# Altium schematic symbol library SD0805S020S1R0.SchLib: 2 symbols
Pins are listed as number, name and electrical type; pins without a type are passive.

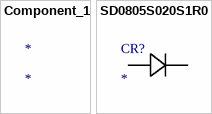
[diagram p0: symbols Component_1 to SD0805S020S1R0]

## Component_1
designator *

## SD0805S020S1R0
designator CR?
No Description Available; Mfr_Name: KYOCERA AVX
footprint SD0805_AVX
pins: 1, 2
